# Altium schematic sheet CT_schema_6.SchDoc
size 311 x 298 mm
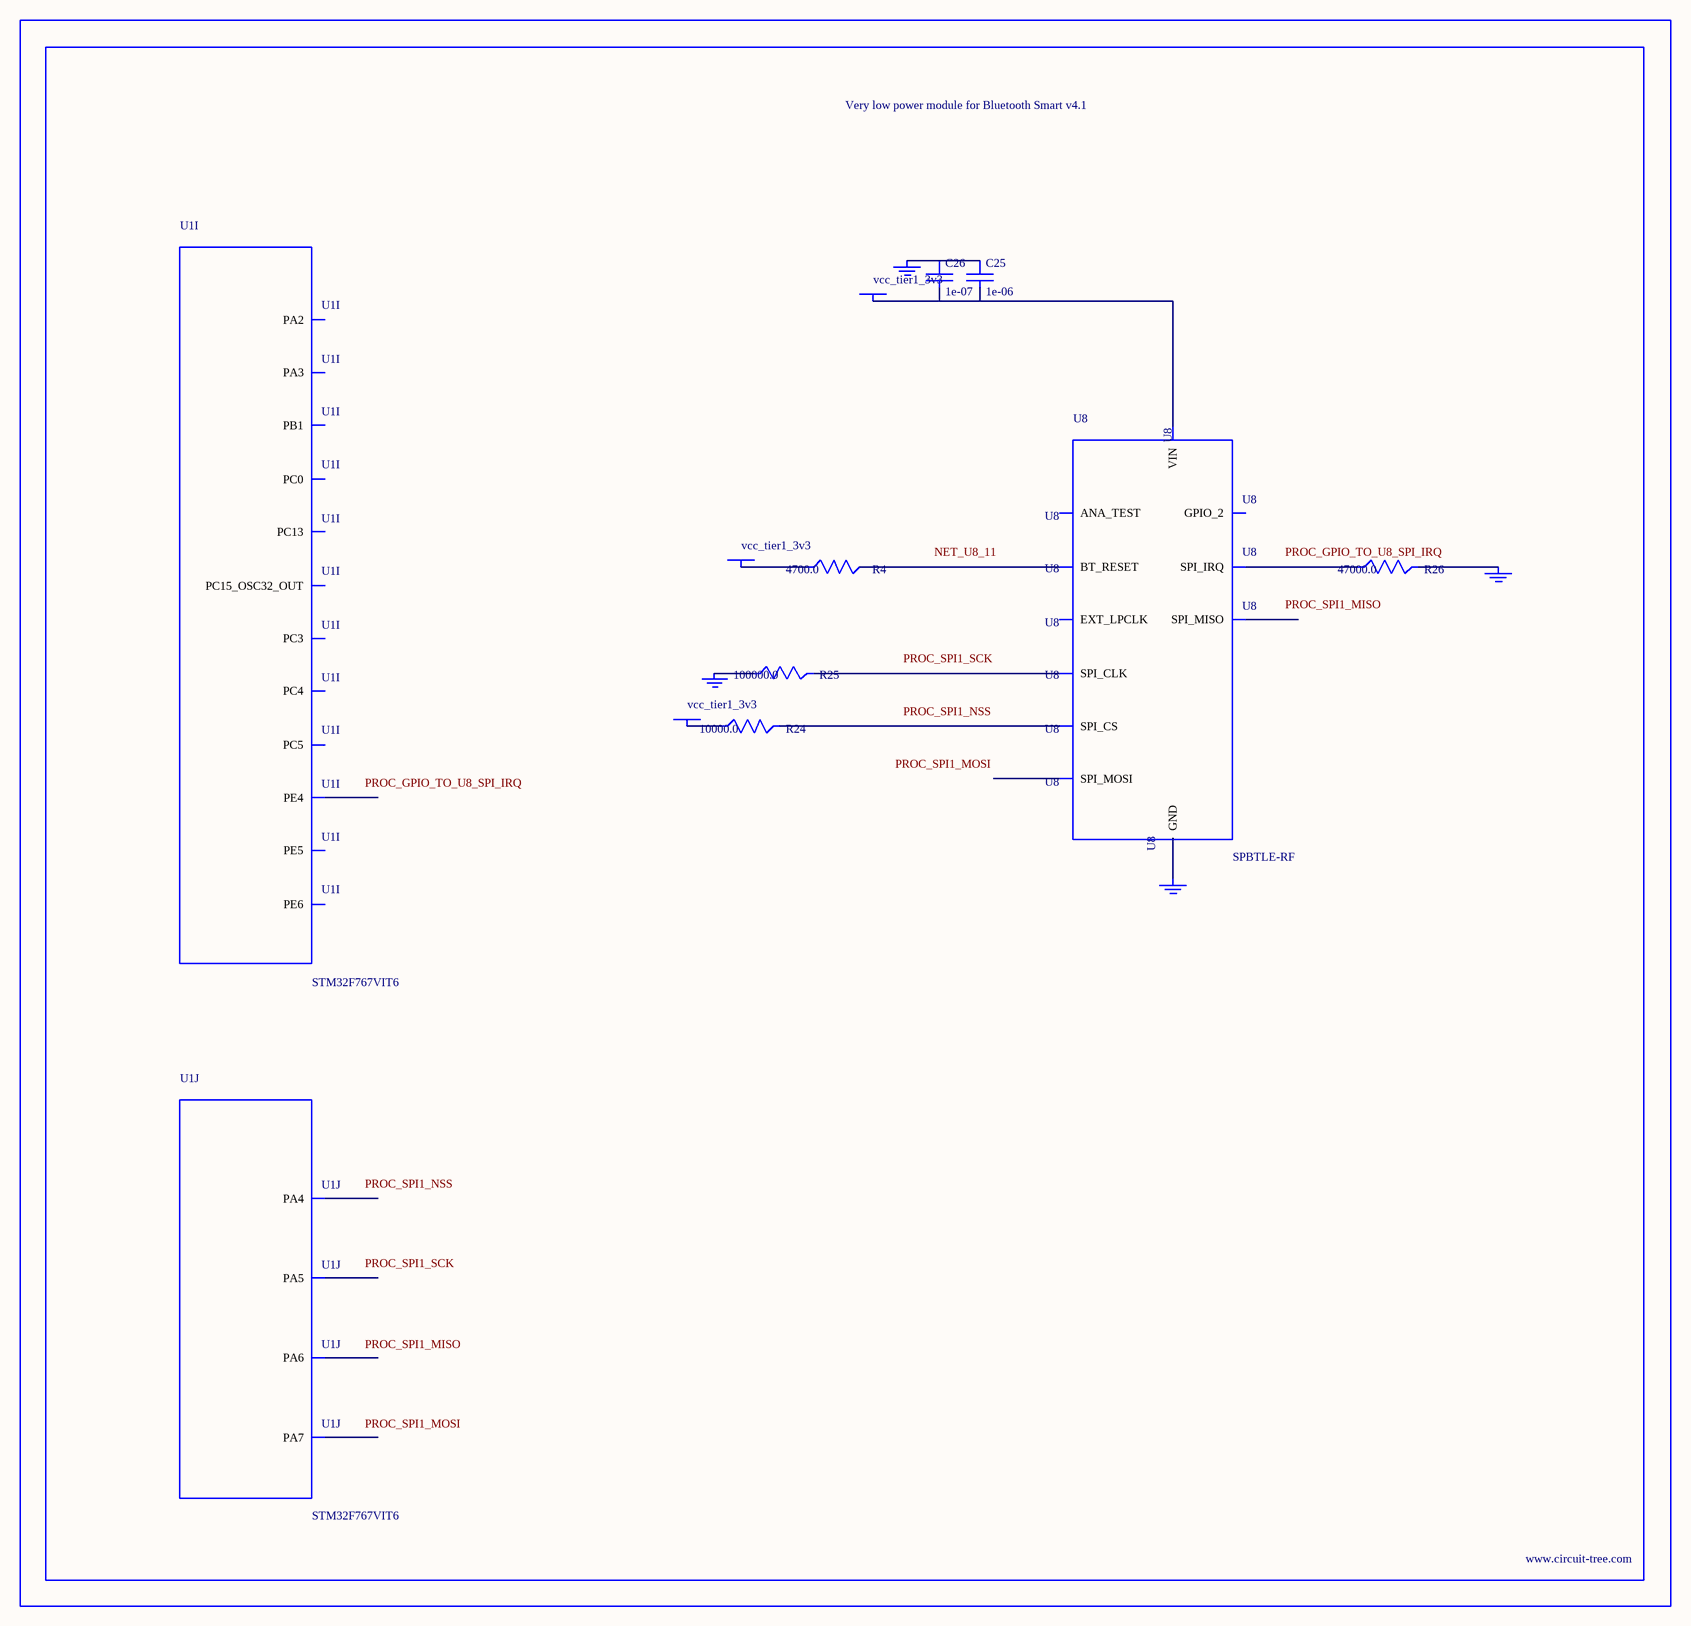
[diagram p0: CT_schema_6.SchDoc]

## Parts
BORDER5  (no value)
C25  1e-06  [C0603]
C26  1e-07  [C0402]
GND_INSTANCE_5_0  (no value)
GND_INSTANCE_5_1  (no value)
GND_INSTANCE_5_2  (no value)
GND_INSTANCE_5_3  (no value)
POWER_INSTANCE_5_0  vcc_tier1_3v3
POWER_INSTANCE_5_1  vcc_tier1_3v3
POWER_INSTANCE_5_2  vcc_tier1_3v3
R4  4700.0  [R0603]
R24  10000.0  [R0603]
R25  100000.0  [R0603]
R26  47000.0  [R0603]
U1  STM32F767VIT6  [LQFP100]  (parts I,J of 11)
U8  SPBTLE-RF  [XCVR_SPBTLE-RF]

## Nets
NetC25_1: C25.1 C26.1 GND_INSTANCE_5_1.0(GND)
NetC25_2: C25.2 C26.2 POWER_INSTANCE_5_0.0(PWR) U8.5(VIN)
NetGND_INSTANCE_5_0_0: GND_INSTANCE_5_0.0(GND) R26.2
NetGND_INSTANCE_5_2_0: GND_INSTANCE_5_2.0(GND) R25.1
NetGND_INSTANCE_5_3_0: GND_INSTANCE_5_3.0(GND) U8.6(GND)
NetPOWER_INSTANCE_5_1_0: POWER_INSTANCE_5_1.0(PWR) R24.1
NetPOWER_INSTANCE_5_2_0: POWER_INSTANCE_5_2.0(PWR) R4.1
NetR4_2: R4.2 U8.11(BT_RESET)
NetR24_2: R24.2 U8.10(SPI_CS)
NetR25_2: R25.2 U8.7(SPI_CLK)
NetR26_1: R26.1 U8.4(SPI_IRQ)

Not connected (* = marked no-connect by the designer): U1 3(PE4) 4(PE5) 5(PE6) 7(PC13) 9(PC15_OSC32_OUT) 15(PC0) 18(PC3) 24(PA2) 25(PA3) 28(PA4) 29(PA5) 30(PA6) 31(PA7) 32(PC4) 33(PC5) 35(PB1); U8 1(EXT_LPCLK) 2(GPIO_2) 3(ANA_TEST) 8(SPI_MISO) 9(SPI_MOSI)

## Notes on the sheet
- Labels drawn without touching a wire or pin: NET_U8_11, PROC_GPIO_TO_U8_SPI_IRQ, PROC_SPI1_MISO, PROC_SPI1_MOSI, PROC_SPI1_NSS, PROC_SPI1_SCK

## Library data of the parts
BORDER5 = BORDER_PAGE5
C25 = C0603C105K3RACTU
C26 = C0402C104K3RACTU
GND_INSTANCE_5_0-GND_INSTANCE_5_3 = GND
POWER_INSTANCE_5_0-POWER_INSTANCE_5_2 = PWR
R4 = RC0603JR-074K7L
R24 = RC0603JR-0710KL
R25 = RC0603JR-07100KL
R26 = RC0603JR-0747KL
